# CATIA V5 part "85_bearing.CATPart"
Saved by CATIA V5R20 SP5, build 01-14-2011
Part number: 85_bearing
Bounding box of the stored display mesh (mm): x -13.957 to 13.957, y 19.362 to 47.362, z -150.1 to -142.1
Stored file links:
  C:\Documents and Settings\anizard\Bureau\13\85_bearing.CATPart
  C:\Documents and Settings\anizard\Bureau\13\anizard.CATProduct
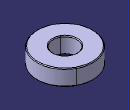
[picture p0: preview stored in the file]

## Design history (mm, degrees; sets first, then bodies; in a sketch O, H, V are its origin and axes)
Set1
  Plane1: linked copy from another document
  Point1: linked copy from another document
  Line1: linked copy from another document
  Point2: linked copy from another document
  Plane2: linked copy from another document
  Plane3: linked copy from another document
Body1 (main body)
  Sketch1 on Plane1, origin (0, 0, 0), H (0, 1, 0), V (0, 0, 1)
    line L1 (39.7155, -142.1) -> (47.0084, -142.1)
    line L2 (47.3619, -142.4536) -> (47.3619, -149.7464)
    line L3 (47.0084, -150.1) -> (39.7155, -150.1)
    line L4 (39.3619, -149.7464) -> (39.3619, -142.4536)
    line L5 (47.3619, -149.7464) -> (47.0084, -150.1)
    line L6 (47.0084, -142.1) -> (47.3619, -142.4536)
    line L7 (39.7155, -142.1) -> (39.3619, -142.4536)
    line L8 (39.3619, -149.7464) -> (39.7155, -150.1)
    reference intersected line E1 through (0, -142.1) direction (1, 0) from Plane2
    reference intersected line E2 through (0, -150.1) direction (1, 0) from Plane3
    reference projected point E3 (39.3619, -70.2938) from Point1
    reference projected point E4 (47.3619, -70.2938) from Point2
    angle L2 L5 = 45
    length L5 = 0.5
    angle L1 L6 = 45
    length L6 = 0.5
    angle L1 L7 = 45
    length L7 = 0.5
    angle L4 L8 = 45
    length L8 = 0.5
    horizontal: L1 H, L3 H
    vertical: L2 V, L4 V
    coincidence: L1 E1, L3 E2, L4 E3, L2 E4
  Shaft1: profile Sketch1, axis Line1, angle 360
